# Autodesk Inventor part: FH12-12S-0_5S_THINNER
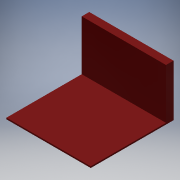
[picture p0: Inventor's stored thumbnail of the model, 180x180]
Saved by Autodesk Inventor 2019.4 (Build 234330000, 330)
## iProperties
Created: 2019-11
Part Number: FH12-12S-0_5S_THINNER
Material: Generic
Document SubType Name: Modeling
Designer: Willist
Density: 1 g/cm^3
Appearance: FH12-12S-0_5SH_THINER, FH12-12S-0_5S_THINNER
Author: Willist
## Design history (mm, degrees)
sketch "FH12-12S-0_5SH_THINER, FH12-12S-0_5S_THINNER_145"
  geometry: L1 (-5.6, 3.95)-(5.6, 3.95); L2 (5.6, 3.95)-(5.6, -2.9); L3 (5.6, -2.9)-(-5.6, -2.9); L4 (-5.6, -2.9)-(-5.6, 3.95)
  constraints: 8 end point
extrude "Extrusion1" join sketch "FH12-12S-0_5SH_THINER, FH12-12S-0_5S_THINNER_145" distance "d0" = 1; taper "d1" = 0 deg
sketch "Sketch2"
  geometry: L1 (-5.6, -2.9)-(5.6, -2.9) reference; L2 (5.6, -2.9)-(5.6, 3.95) reference; L3 (-5.6, -2.9)-(5.6, -2.9); L4 (5.6, -2.9)-(5.6, -2.708); L5 (5.6, -2.708)-(-5.6, -2.708); L6 (-5.6, -2.708)-(-5.6, -2.9); 1 further point
  constraints: 8 end point, 2 parallel, 1 horizontal, 1 perpendicular, 1 point on line
extrude "Extrusion2" join sketch "Sketch2" distance "d2" = 10; taper "d3" = 0 deg
body "Solid1"
